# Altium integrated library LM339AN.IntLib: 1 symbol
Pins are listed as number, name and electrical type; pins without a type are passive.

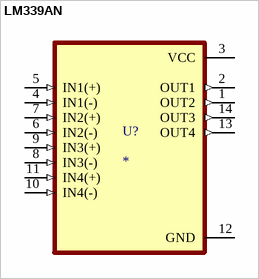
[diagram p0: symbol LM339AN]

## LM339AN
designator U?
Precision quad differential comparator, commercial grade; MF: Texas Instruments; MP: LM339AN
footprint DIP794W45P254L1969H508Q14
pins: 1 OUT2 (out), 2 OUT1 (out), 3 VCC (power), 4 IN1(-) (in), 5 IN1(+) (in), 6 IN2(-) (in), 7 IN2(+) (in), 8 IN3(-) (in), 9 IN3(+) (in), 10 IN4(-) (in), 11 IN4(+) (in), 12 GND (power), 13 OUT4 (out), 14 OUT3 (out)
